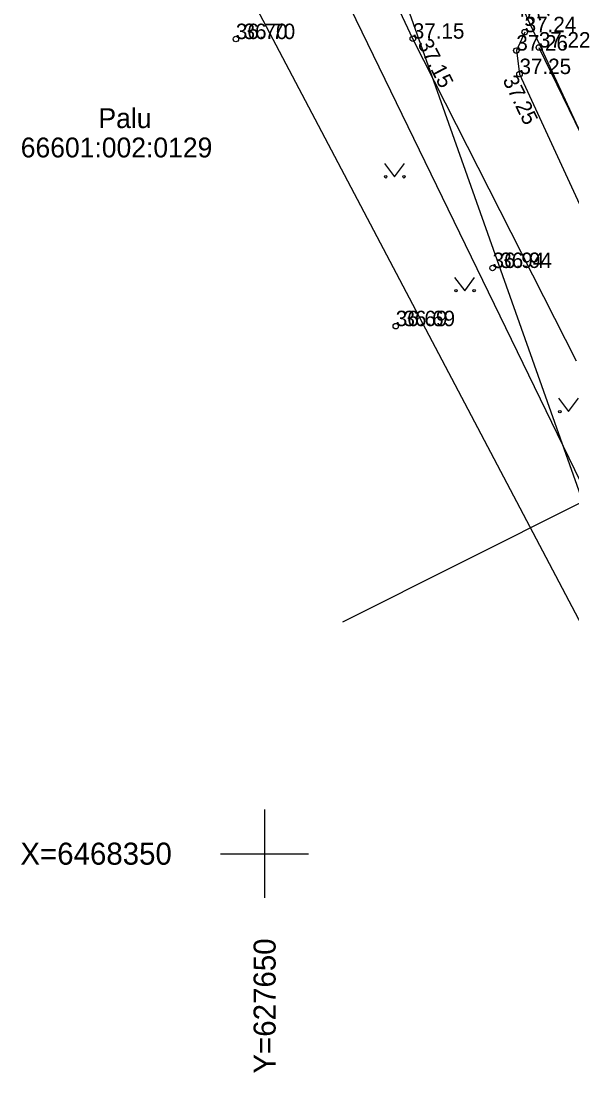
# Model space of a CAD drawing. Extents: x 627548 to 628052, y 6467984 to 6468802.
# Drawn here: x 627638.94 to 627663.96, y 6468340.05 to 6468387.78 of the extents above; entities that cross this region are included whole.
import ezdxf

# ---------------------------------------------------------------- set-up
doc = ezdxf.new("R2010")
doc.units = 0
for name, color, linetype in [('AED', 7, 'Continuous'), ('HALJASTUS', 7, 'Continuous'), ('KORGUS-EH2000', 7, 'Continuous'), ('KTRASS', 7, 'Continuous'), ('MOOTKORG-EH2000', 7, 'Continuous'), ('MOOTMPUNKT', 7, 'Continuous'), ('MPOHULIIN', 7, 'Continuous'), ('PIIR', 7, 'Continuous'), ('SIOHULIIN', 7, 'Continuous'), ('TEE', 7, 'Continuous'), ('VORK', 7, 'Continuous')]:
    doc.layers.add(name, color=color, linetype=linetype)

msp = doc.modelspace()

# ---------------------------------------------------------------- linework, layer by layer
at = {"layer": 'AED'}
msp.add_lwpolyline([(627662.455, 6468386.577), (627666.016, 6468379.277), (627668.267, 6468374.693)], dxfattribs=at)
at = {"layer": 'HALJASTUS'}
for p, q in [((627655.439, 6468381.317), (627655.903, 6468380.711)), ((627655.903, 6468380.711), (627656.348, 6468381.317)), ((627658.624, 6468376.148), (627659.087, 6468375.541)), ((627659.087, 6468375.541), (627659.533, 6468376.148)), ((627663.344, 6468370.664), (627663.807, 6468370.057)), ((627663.807, 6468370.057), (627664.253, 6468370.664))]:
    msp.add_line(p, q, dxfattribs=at)
for centre in [(627655.501, 6468380.711), (627656.33, 6468380.711), (627658.686, 6468375.541), (627659.515, 6468375.541), (627663.406, 6468370.057)]:
    msp.add_circle(centre, 0.055, dxfattribs=at)
at = {"layer": 'KTRASS'}
msp.add_lwpolyline([(627669.837, 6468355.594), (627653.907, 6468388.368), (627661.842, 6468392.243)], dxfattribs=at)
at = {"layer": 'MOOTMPUNKT'}
for centre in [(627656.73, 6468386.978), (627661.81, 6468387.273), (627648.696, 6468386.96), (627662.455, 6468386.577), (627661.432, 6468386.438), (627661.576, 6468385.372), (627660.353, 6468376.573), (627655.957, 6468373.935)]:
    msp.add_circle(centre, 0.125, dxfattribs=at)
at = {"layer": 'MPOHULIIN'}
msp.add_lwpolyline([(627647.118, 6468393.14), (627668.977, 6468351.69)], dxfattribs=at)
at = {"layer": 'PIIR'}
for p, q in [((627664.45, 6468365.98), (627644.75, 6468421.52)), ((627668.1, 6468374.6), (627655.45, 6468401.9)), ((627653.556, 6468360.522), (627664.45, 6468365.98))]:
    msp.add_line(p, q, dxfattribs=at)
at = {"layer": 'SIOHULIIN'}
msp.add_lwpolyline([(627647.118, 6468393.14), (627668.977, 6468351.69)], dxfattribs=at)
at = {"layer": 'TEE'}
for points in [[(627664.163, 6468372.339), (627656.73, 6468386.978), (627654.281, 6468392.2), (627651.487, 6468398.488), (627650.055, 6468402.405), (627646.281, 6468409.175), (627642.033, 6468417.224), (627639.524, 6468421.265)], [(627661.81, 6468387.273), (627661.432, 6468386.438), (627661.576, 6468385.372), (627665.021, 6468377.889), (627666.738, 6468374.679), (627667.521, 6468373.774)]]:
    msp.add_lwpolyline(points, dxfattribs=at)
at = {"layer": 'VORK'}
for p, q in [((627650, 6468352), (627650, 6468348)), ((627648, 6468350), (627652, 6468350))]:
    msp.add_line(p, q, dxfattribs=at)

# ---------------------------------------------------------------- texts
at = {"layer": 'KORGUS-EH2000'}
for s, rotation, p in [('37.24', 28.0115, (627661.879, 6468387.468)), ('37.15', 297.0315, (627656.928, 6468386.758)), ('37.25', 295.975, (627660.794, 6468385.105))]:
    msp.add_text(s, height=0.7, rotation=rotation, dxfattribs=at).set_placement(p)
for s, p in [('36.70', (627649.046, 6468386.96)), ('36.94', (627660.703, 6468376.573)), ('36.69', (627656.307, 6468373.935))]:
    msp.add_text(s, height=0.7, dxfattribs=at).set_placement(p)
at = {"layer": 'MOOTKORG-EH2000'}
for s, p in [('36.70', (627648.696, 6468386.96)), ('37.15', (627656.73, 6468386.978)), ('37.24', (627661.81, 6468387.273)), ('37.26', (627661.432, 6468386.438)), ('37.22', (627662.455, 6468386.577)), ('37.25', (627661.576, 6468385.372)), ('36.94', (627660.353, 6468376.573)), ('36.69', (627655.957, 6468373.935))]:
    msp.add_text(s, height=0.7, dxfattribs=at).set_placement(p)
at = {"layer": 'PIIR'}
for s, p in [('Palu', (627642.455, 6468382.922)), ('66601:002:0129', (627638.925, 6468381.591))]:
    msp.add_text(s, height=0.9, dxfattribs=at).set_placement(p)
at = {"layer": 'VORK'}
msp.add_text('X=6468350 ', height=1, dxfattribs=at).set_placement((627638.908, 6468349.5))
msp.add_text('Y=627650 ', height=1, rotation=90, dxfattribs=at).set_placement((627650.5, 6468340.021))

doc.saveas('drawing.dxf')
